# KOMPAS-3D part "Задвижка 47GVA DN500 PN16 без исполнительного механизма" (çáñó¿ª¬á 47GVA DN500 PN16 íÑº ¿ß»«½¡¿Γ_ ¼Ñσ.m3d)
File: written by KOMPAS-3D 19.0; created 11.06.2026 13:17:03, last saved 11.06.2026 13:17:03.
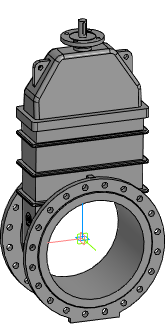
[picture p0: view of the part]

Document properties: Автор: Евгений; Полное имя файла: Z:\3.Личные\kachalov\001_3d для проектировщиков\2.2 Тип 47GVA, 47GVA.Z\_stp\_stp_Задвижка 47GVA DN40-DN1000 без исп.мех\Задвижка 47GVA DN500 PN16 без исполнит_ мех.m3d

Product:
- Part/product: Задвижка 47GVA DN500 PN16 без исполнительного механизма

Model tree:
1. Операция без истории:1  (labels: Задвижка 47GVA DN500 PN16 без исполнительного механизма)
